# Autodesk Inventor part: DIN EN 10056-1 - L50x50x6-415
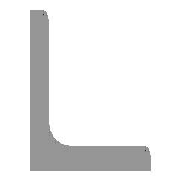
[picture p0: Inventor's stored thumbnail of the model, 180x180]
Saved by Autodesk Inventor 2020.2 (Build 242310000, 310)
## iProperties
Created: 2019-01
Part Number: DIN EN 10056-1 - L50x50x6-415
Material: Stahl, weich
Description: Warmgewalztes Baustahlprofil - gleichschenklig
Document SubType Name: Modeling
Standard: DIN
Designer: lutzd
Standard Revision: 1998
Standards Organization: DIN
Language: de-DE
Size Designation: L50x50x6
Categories: <MemberInstance><Categories><Category DisplayName="Profile" InternalName="089c4875-fa83-4c05-b084-43b9cc11f5ed" Mnemonic="GRDR"><CategoryParameter DisplayName="
Stock Number: L50x50x6
Mass: 1823.55 g
Surface Area: 813.077 cm^2
Volume: 232.299 cm^3
Density: 7.85 g/cm^3
Appearance: Semi-Polished(8)
IsCustomPart: 1
_CCFamilyMember: 120
_CCFamilyDisplayName: DIN EN 10056-1 (Warmgewalztes Baustahlprofil - gleichschenklig) - Warmgewalztes Baustahlprofil - gleichschenklig
_FrameMemberDoc: Frame Member File
_Version: 15.0.0
_GetPNFromCC: 1
G_L: 415,000 mm
G_W: 50,000 mm
G_H: 50,000 mm
+E179E4BB-297D-4501-98DC-17FF071DEA19+SCHNITTDETAIL1: Schnittwinkel 90,00 grd
+F8C8B184-AED8-4B88-B418-57FBFD543CC6+SCHNITTDETAIL2: Schnittwinkel 90,00 grd
DocNumber: ADSK-014306
Folder: .
Dimensions: 50x415x50 mm
Mass: 1,824 kg
VLT_Material: Stahl, weich
Title: Profil-Bauteil
Author: lutzd
Revision Number: -
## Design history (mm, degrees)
node "Startebene"
node "Endebene"
sketch "Skizze"
  geometry: L1 (-8.414, -1.414)-(-8.414, 32.086); L2 (-14.414, 35.586)-(-11.914, 35.586); L3 (-14.414, -14.414)-(-14.414, 35.586); L4 (-14.414, -14.414)-(35.586, -14.414); L5 (35.586, -11.914)-(35.586, -14.414); L6 (-1.414, -8.414)-(32.086, -8.414); L7 (0, 46.456)-(0, -24.559) reference; L8 (-24.559, 0)-(46.456, 0) reference; A1 r 7 centre (-1.414, -1.414) between (-8.414, -1.414) and (-1.414, -8.414); A2 r 3.5 centre (-11.914, 32.086) between (-8.414, 32.086) and (-11.914, 35.586); A3 r 3.5 centre (32.086, -11.914) between (35.586, -11.914) and (32.086, -8.414); 3 further points
  constraints: 12 end point, 6 point on circle, 6 point on line, 6 tangent, 3 centre point, 3 horizontal, 3 vertical, 1 equal radius
  dimensions: "d4" = 50 distance of L3.start L4.end (= b); "d6" = 50 distance of L3.start L2.start (= b); "d8" = 6 distance of point (35.586, -8.414) L4.end (= ParT); "d10" = 6 distance of L2.start point (-8.414, 35.586) (= ParT); "d17" = 7 radius of A1 (= R); "d18" = 3.5 radius of A2 (= R1); "d19" = 14.41385 distance between parallel lines of L8 L4 (= ex); "d20" = 14.41385 distance between parallel lines of L3 L7 (= d19)
extrude "Körper" new body sketch "Skizze" stored distance "d11" = 415 (= G_L); taper "d12" = 0 deg
node "Driven Length"
  sketch "Sketch3"
    geometry: L1 (0, 0)-(10, 0) reference
    constraints: 2 end point, 1 horizontal
  workplane "Work Plane10"
  sketch "Sketch4"
    geometry: L1 (-2, 25)-(12, 25) reference; L2 (-2, 440)-(12, 440) reference
    dimensions: "d24" = 415 distance between parallel lines of L1 L2 (derived)
workplane "Arbeitsebene11"
feature "Trennen1"
workplane "Arbeitsebene12"
feature "Trennen2"
sketch "Skizze5"
  geometry: L1 (301, -14.5)-(276, -14.5); L2 (301, -9.5)-(276, -9.5); L3 (276, -19.5)-(301, -19.5); L4 (139, -14.5)-(114, -14.5); L5 (139, -9.5)-(114, -9.5); L6 (114, -19.5)-(139, -19.5); L7 (415, -50)-(415, 0) reference; L8 (0, 0)-(415, 0) reference; L9 (0, -50)-(0, 0) reference; A1 r 5 centre (301, -14.5) between (301, -19.5) and (301, -9.5); A2 r 5 centre (276, -14.5) between (276, -9.5) and (276, -19.5); A3 r 5 centre (139, -14.5) between (139, -19.5) and (139, -9.5); A4 r 5 centre (114, -14.5) between (114, -9.5) and (114, -19.5); 4 further points
  constraints: 16 end point, 8 point on circle, 8 tangent, 4 centre point, 3 midpoint, 2 parallel, 2 point on line, 1 horizontal
  dimensions: "d25" = 162 distance of point (288.5, -14.5) point (126.5, -14.5); "d27" = 14.5 distance between parallel lines of L8 L1; "d28" = 10 distance between parallel lines of L2 L3; "d29" = 25 distance of L1.start L1.end; "d30" = 10 distance between parallel lines of L5 L6 (= d28); "d31" = 25 distance of L4.start L4.end (= d29); "d35" = 81 horizontal distance of point (288.5, -14.5) point (207.5, 0) (= 0.5 x d25)
extrude "Extrusion2" cut sketch "Skizze5" distance "d32" = 10; taper "d33" = 0 deg
body "Solid1"
other parameters: "b" = 50 [user parameter; used in 3 equation terms], "ParT" = 6 [user parameter; used in 3 equation terms], "R" = 7 [user parameter; used in 1 equation term], "R1" = 3.5 [user parameter; used in 1 equation term], "G_L" = 415 (= d24) [user parameter; used in 1 equation term], "d7" = 4 (derived), "d9" = 4 (derived), "ex" = 14.41385 (computed from b, ParT) [user parameter; used in 1 equation term], "G_OFFSET_START" = -25 [user parameter; used in 1 equation term], "d21" = 25 (= -G_OFFSET_START), "d23" = 90 deg
